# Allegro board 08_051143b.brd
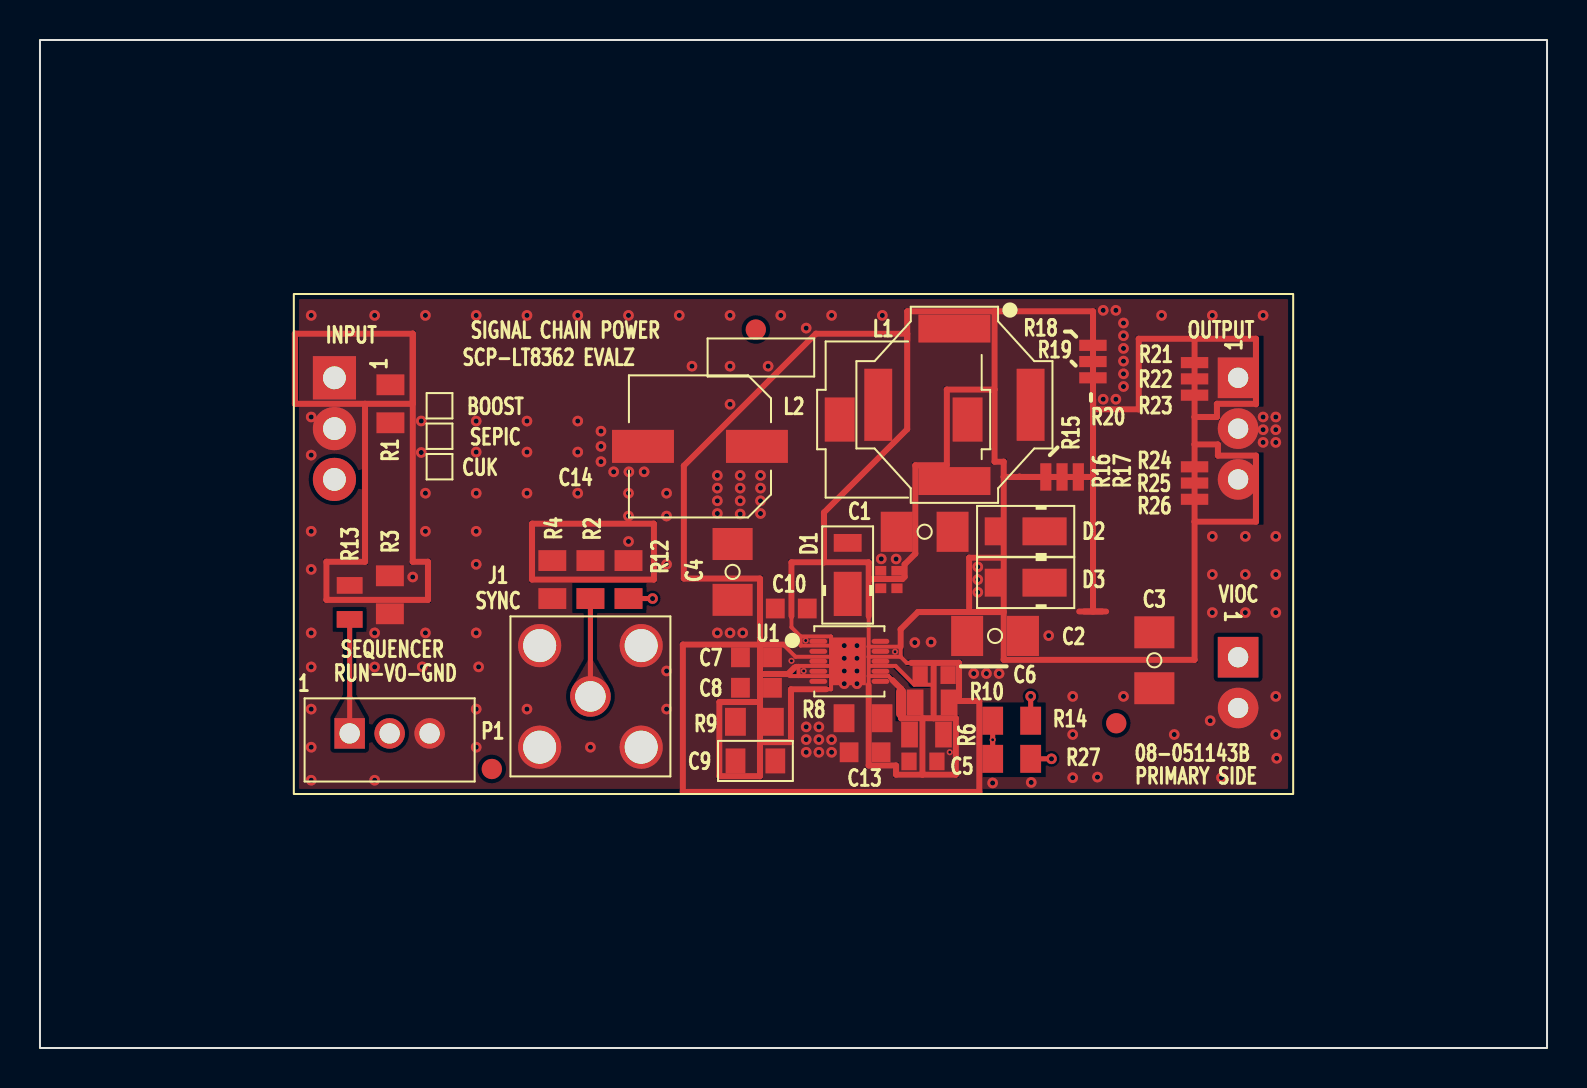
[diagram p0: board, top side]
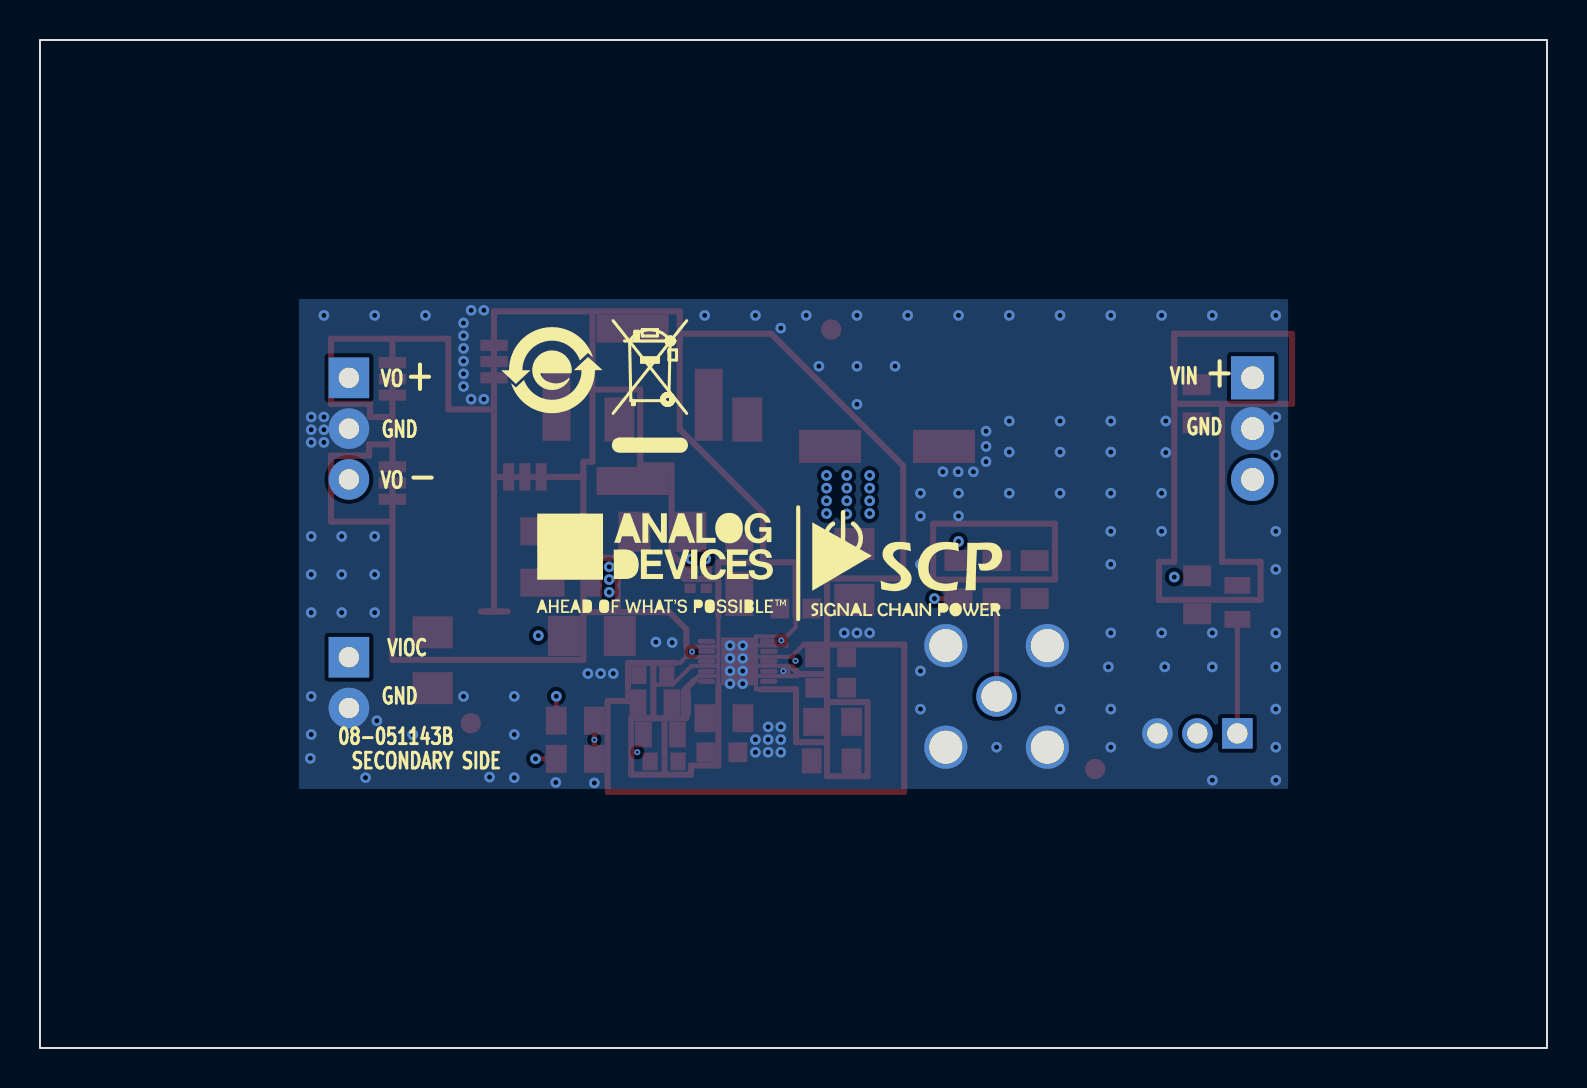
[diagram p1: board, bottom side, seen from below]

Outline 75.4 x 50.4 mm; copper layers: TOP, L2, L3, BOTTOM. Coordinates in mm from the lower left corner of the outline.
Outline path: rectangle 0,0 75.4,50.4

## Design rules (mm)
constraint set DEFAULT: min track width 0.203

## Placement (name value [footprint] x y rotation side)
C1  1uF  [C1206H71]  44.26 25.81 180 top
C2  10UF  [C1206H71]  47.78 20.6 180 top
C3  10UF  [C1206H71]  55.75 19.39 270 top
C4  10UF  [C1206H71]  34.65 23.8 270 top
C5  TBD0603  [C0603#2]  44.18 14.33 180 top
C6  0.22UF  [C0603#2]  44.74 18.65 0 top
C7  1UF  [C0603]  35.85 19.54 180 top
C8  TBD0603  [C0603]  35.85 18.01 180 top
C9  1.5NF  [C0805-2]  35.79 14.35 0 top
C10  1UF  [C0603]  37.59 21.97 0 top
C11  0.1UF  [C0402]  42.06 23.42 90 top
C12  0.1UF  [C0402]  42.88 23.42 90 top
C13  TBD0603  [C0603]  41.28 14.79 180 top
C14  33UF  [CPLSMSQ260H315]  33.02 30.08 180 top
D1  DFLS260-7  [POWERDI123]  40.41 23.65 90 top
D2  DFLS260-7  [POWERDI123]  49.32 25.83 180 top
D3  DFLS260-7  [POWERDI123]  49.32 23.27 180 top
INPUT  PBC03SBAN  [CNTHMHDRRA1X3L300W100H145]  14.73 33.51 270 top
J1  5-1814832-1  [CNTYCO1814832]  27.54 17.58 0 top
L1  6.8UH  [LSMSQ315H83]  45.75 32.16 270 top
L2  6.8UH  [LSMSQ287H138]  43.21 31.42 0 top
NOREF  -  [unnamed]  53.85 16.24 0 top
NOREF#2  -  [#2]  -137.79 189.21 0 top
NOREF#3  -  [#2]  12.7 12.7 0 top
NOREF#4  -  [#2]  62.85 37.77 180 top
NOREF#5  -  [#2]  -223.77 -182.39 0 top
NOREF#6  -  [#2]  38.28 64.9 0 top
NOREF#7  -  [#2]  92.84 143.87 0 top
NOREF#8  -  [#2]  -336.95 -273.25 0 top
NOREF#9  -  [#2]  -287.53 151.49 0 top
NOREF#10  -  [#2]  62.7 12.7 90 top
NOREF#11  -  [#2]  -336.95 -273.25 0 top
NOREF#12  -  [#2]  12.68 12.75 0 top
NOREF#13  -  [#2]  117.03 50.84 0 top
NOREF#14  -  [#2]  62.72 12.75 90 top
NOREF#15  -  [#2]  12.68 37.77 270 top
NOREF#16  -  [unnamed]  35.81 35.92 0 top
NOREF#17  -  [#2]  -187.71 -197.76 0 top
NOREF#18  -  [unnamed]  22.61 13.95 0 top
NOREF#19  -  [#2]  49.78 33.89 180 bottom
NOREF#20  -  [#2]  45.09 29.83 180 bottom
NOREF#21  -  [#2]  44.61 24.22 180 bottom
NOREF#22  -  [#2]  32 24.24 180 bottom
OUTPUT  PPPC031LGBN-RC  [CNHDRRA1X3H108]  59.94 33.51 270 top
P1  53253-0370  [CNTHMHDR1X3L315W144H224]  15.49 15.73 0 top
R1  1MEG  [R0805]  17.53 32.21 270 top
R2  0  [R0805]  27.54 23.42 90 top
R3  TBD0805  [R0805]  17.51 22.66 270 top
R4  0  [R0805]  25.63 23.42 90 top
R6  1MEG  [R0805#2]  44.35 15.68 180 top
R8  71.5K  [R0805]  41.18 16.49 180 top
R9  40.2K  [R0805]  35.74 16.31 180 top
R10  20K  [R0805#2]  44.63 17.28 0 top
R12  0  [R0805]  29.44 23.42 90 top
R13  TBD0805  [R0805#2]  15.49 22.28 90 top
R14  0  [R0805]  48.62 16.36 180 top
R15  -  [NC0402L]  50.32 28.55 270 top
R16  -  [NC0402L]  51.14 28.55 270 top
R17  -  [NC0402L]  51.95 28.55 270 top
R18  -  [NC0402L]  52.68 35.13 0 top
R19  -  [NC0402L]  52.68 34.32 0 top
R20  -  [NC0402L]  52.68 33.51 0 top
R21  -  [NC0402L]  57.77 34.27 0 top
R22  -  [NC0402L]  57.77 33.46 0 top
R23  -  [NC0402L]  57.77 32.64 0 top
R24  -  [NC0402L]  57.77 29.06 0 top
R25  -  [NC0402L]  57.77 28.25 0 top
R26  -  [NC0402L]  57.77 27.44 0 top
R27  0  [R0805]  48.62 14.46 0 top
U1  LT8362EDD#PBF  [DFN10_3X3_PAD2_38X1_64]  40.49 19.33 270 top
VIOC  PPPC021LGBN-RC  [CNTHFHDRRA1X2L220W335H108]  59.94 19.54 270 top

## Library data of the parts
C1 = CAP: Tolerance: 10; User Part Number: UPN; alternate symbols: (); part number: CAP_SM-1UF,100V,10,E023069,C1206H71; tolerance: 10
C2-C4 = CAP: Tolerance: 20; User Part Number: UPN; alternate symbols: (); part number: CAP_SM-10UF,50V,20,E035601,C1206H71; tolerance: 20
C5 C8 C13 = CAP: User Part Number: UPN; alternate symbols: (C0603L, C0603L_ALT); part number: CAP_SM-TBD0603,TBD0603,TBD0603,E000382,C0603
C6 = CAP: Tolerance: 10; User Part Number: UPN; alternate symbols: (C0603L, C0603L_ALT); part number: CAP_SM-0.22UF,25V,10,E028829,C0603; tolerance: 10
C7 C10 = CAP: User Part Number: UPN; Tolerance: 10; alternate symbols: (); part number: CAP_SM-1UF,50V,10,E034224,C0603; tolerance: 10
C9 = CAP: Tolerance: 10; User Part Number: UPN; alternate symbols: (); part number: CAP_SM-1.5NF,25V,10,E033704,C0805-2; tolerance: 10
C11 C12 = CAP: Tolerance: 10; User Part Number: UPN; alternate symbols: (C0402L_ALT); part number: CAP_SM-0.1UF,50V,10,E038292,C0402; tolerance: 10
C14 = CAPP: Tolerance: 20; User Part Number: UPN; alternate symbols: (); part number: CAPP_SM-33UF,50V,20,E035519,CPLSMSQ260H315; tolerance: 20
D1-D3 = DIOSCHOTTKY: User Part Number: UPN; Tolerance: N/A; alternate symbols: (); part number: DIOSCHOTTKY_SM-DFLS260-7,60V,N/A,E032987,POWERDI123; tolerance: N/A
INPUT = CN3P: Tolerance: N/A; User Part Number: UPN; alternate symbols: (CNTHMHDRRA1X3L300W100H145_SCP); part number: CN3P_TH-PBC03SBAN,E034137,CNTHMHDRRA1X3L300W100H145; tolerance: N/A
J1 = CNBNC5P: Tolerance: N/A; User Part Number: UPN; alternate symbols: (); part number: CNBNC5P_TH-5-1814832-1,E010606,CNTYCO1814832; tolerance: N/A
L1 = IND_4P_V11: Tolerance: 30; User Part Number: UPN; alternate symbols: (); part number: IND_4P_V11_SM-6.8UH,30,E033529,LSMSQ315H83; tolerance: 30
L2 = IND: Tolerance: 20; User Part Number: UPN; alternate symbols: (); part number: IND_SM-6.8UH,20,E033705,LSMSQ287H138; tolerance: 20
OUTPUT = CN3P: User Part Number: UPN; Tolerance: N/A; alternate symbols: (CNHDRRA1X3H108_SCP); part number: CN3P_TH-PPPC031LGBN-RC,E034111,CNHDRRA1X3H108; tolerance: N/A
P1 = CN3P: Tolerance: N/A; User Part Number: UPN; alternate symbols: (); part number: CN3P_TH-53253-0370,E033940,CNTHMHDR1X3L315W144H224; tolerance: N/A
R1 = RES: User Part Number: UPN; Tolerance: 5; alternate symbols: (); part number: RES_SM-1MEG,E033749,1/8W,5,R0805; tolerance: 5
R2 R4 R12 R14 R27 = RES: User Part Number: UPN; Tolerance: N/A; alternate symbols: (R0805L); part number: RES_SM-0,E030875,1/8W,N/A,R0805; tolerance: N/A
R3 R13 = RES: User Part Number: UPN; alternate symbols: (R0805L); part number: RES_SM-TBD0805,E004051,TBD0805,TBD0805,R0805
R6 = RES: User Part Number: UPN; Tolerance: 1; alternate symbols: (R0805L); part number: RES_SM-1MEG,E003518,1/8W,1,R0805; tolerance: 1
R8 = RES: User Part Number: UPN; Tolerance: 1; alternate symbols: (R0805L); part number: RES_SM-71.5K,E005326,1/8W,1,R0805; tolerance: 1
R9 = RES: User Part Number: UPN; Tolerance: 0.1; alternate symbols: (R0805L); part number: RES_SM-40.2K,E018845,1/5W,0.1,R0805; tolerance: 0.1
R10 = RES: User Part Number: UPN; Tolerance: 1; alternate symbols: (R0805L); part number: RES_SM-20K,E003539,1/8W,1,R0805; tolerance: 1
R15-R26 = NC2P: User Part Number: UPN; Tolerance: N/A; alternate symbols: (); part number: NC2P_SM-NC0402L,E033984,NC0402L; tolerance: N/A
U1 = ICLT8362: Tolerance: N/A; User Part Number: UPN; alternate symbols: (); part number: ICLT8362_SM-LT8362EDD#PBF,E033516,DFN10_3X3_PAD2_38X1_64; tolerance: N/A
VIOC = CN2P: Tolerance: N/A; User Part Number: UPN; alternate symbols: (CNTHFHDRRA1X2L220W335H108_SCP); part number: CN2P_TH-PPPC021LGBN-RC,E034113,CNTHFHDRRA1X2L220W335H108; tolerance: N/A

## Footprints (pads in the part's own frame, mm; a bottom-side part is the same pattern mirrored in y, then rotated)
C0402
  rect 0.483x0.559 smd: 1(-0.438,0) 2(0.438,0)
C0603
  rect 0.94x0.991 smd: 1(-0.8,0) 2(0.8,0)
C0603#2
  rect 0.762x0.889 smd: 1(-0.699,0) 2(0.699,0)
C0805-2
  rect 0.991x1.245 smd: 1(-0.995,0) 2(0.995,0)
C1206H71
  rect 1.6x2.007 smd: 1(-1.397,0) 2(1.397,0)
CNHDRRA1X3H108
  rect 2.032x2.032 hole 1.016: 1(0,0)
  round 2.032 hole 1.016: 2(2.54,0) 3(5.08,0)
CNTHFHDRRA1X2L220W335H108
  rect 2.032x2.032 hole 1.016: 1(0,0)
  round 2.032 hole 1.016: 2(2.54,0)
CNTHMHDR1X3L315W144H224
  rect 1.524x1.524 hole 1.016: 1(0,0)
  round 1.524 hole 1.016: 2(2,0) 3(4,0)
CNTHMHDRRA1X3L300W100H145
  rect 2.159x2.159 hole 1.143: 1(0,0)
  round 2.159 hole 1.143: 2(2.54,0) 3(5.08,0)
CNTYCO1814832
  round 2.032 hole 1.524: 1(0,0)
  round 2.159 hole 1.651: 2(-2.54,2.54) 3(2.54,2.54) 4(2.54,-2.54) 5(-2.54,-2.54)
CPLSMSQ260H315
  rect 3.099x1.651 smd: N(2.85,0) P(-2.85,0)
DFN10_3X3_PAD2_38X1_64
  oval 0.254x0.889 smd: 1(-1,-1.555) 2(-0.5,-1.555) 3(0,-1.555) 4(0.5,-1.555) 5(1,-1.555) 6(1,1.555) 7(0.5,1.555) 8(0,1.555) 9(-0.5,1.555) 10(-1,1.555)
  rect 2.388x1.651 smd: PAD(0,0)
LSMSQ287H138
  rect 1.499x2.21 smd: 1(-3.199,0) 2(3.199,0)
LSMSQ315H83
  rect 1.397x3.607 smd: 1(-3.811,0) 3(3.811,0)
  rect 3.607x1.397 smd: 2(0,-3.811) 4(0,3.811)
NC0402L
  rect 0.572x0.559 smd: 1(-0.4,0) 2(0.4,0)
POWERDI123
  rect 0.889x1.397 smd: A(1.606,0)
  rect 2.21x1.397 smd: C(-0.945,0)
R0805
  rect 1.041x1.397 smd: 1(-0.95,0) 2(0.95,0)
R0805#2
  rect 0.838x1.295 smd: 1(-0.85,0) 2(0.85,0)
unnamed
  round 1.016 smd: (0,0)

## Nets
AGND: C2.2(N2) C3.2(N2) C4.2(N2) C6.2(N2) C7.2(N2) C8.2(N2) C9.2(N2) C10.2(N2) C13.2(N2) C14.N(N2) D1.C INPUT.2 J1.2 J1.3 J1.4 J1.5(SH4) OUTPUT.2 P1.3(N3) R3.2(N2) R4.1 R8.2(N2) R10.2(N2) R18.2(N2) R19.2(N2) R20.2(N2) U1.4 U1.PAD VIOC.2(N2)
INTVCC: C7.1 R12.1 U1.3
OUT: C2.1 C3.1 D2.C D3.C P1.2 R14.1 R15.2(N2) R16.2(N2) R17.2(N2) R21.1 R22.1 R23.1 R24.1 R25.1 R26.1
RUN: P1.1 R13.1
SYNC: J1.1 R2.1
UNNAMED_2_CAP_I16_N1: C9.1 R9.2(N2)
UNNAMED_2_CAP_I18_N1: C6.1 U1.8
UNNAMED_2_CAP_I26_N1: C8.1 R9.1 U1.5
UNNAMED_2_CAP_I28_N1: C1.1 C11.1 C12.1 D2.A(P) L1.3 L2.2(N2) U1.10
UNNAMED_2_CAP_I28_N2: C1.2(N2) C11.2(N2) C12.2(N2) D1.A(P) D3.A(P) L1.1
UNNAMED_2_CAP_I41_N1: C5.2(N2) C13.1 R6.2(N2) R8.1 U1.6
UNNAMED_2_CAP_I42_N1: C5.1 R6.1 R14.2(N2) R27.1
UNNAMED_2_ICLT8362_I21_EN: R1.2(N2) R3.1 R13.2(N2) U1.1
UNNAMED_2_ICLT8362_I21_RT: R10.1 U1.7
UNNAMED_2_ICLT8362_I21_SYNC: R2.2(N2) R4.2(N2) R12.2(N2) U1.9
UNNAMED_2_IND4PV11_I25_N4: L1.4(N4) R15.1 R16.1 R17.1 R18.1 R19.1 R20.1
V+: C4.1 C10.1 C14.P INPUT.1 L1.2 L2.1 R1.1 U1.2(VIN)
VIOC: R27.2(N2) VIOC.1
VO+: OUTPUT.1 R21.2(N2) R22.2(N2) R23.2(N2)
VO-: OUTPUT.3(N3) R24.2(N2) R25.2(N2) R26.2(N2)

Pads without a net: INPUT 3

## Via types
v1: diameter 0.305, hole 0.152, TOP to BOTTOM, 6 vias
v2: diameter 0.533, hole 0.254, TOP to BOTTOM, 153 vias

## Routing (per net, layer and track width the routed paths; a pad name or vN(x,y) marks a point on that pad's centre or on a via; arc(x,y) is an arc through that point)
AGND: length 0
  BOTTOM w0: 28.4,24.12 28.4,24.12
  vias: v1(38.21,18.85) v2(13.57,36.63) v2(13.57,31.55) v2(13.57,29.65) v2(13.57,25.84) v2(13.57,23.93) v2(13.57,20.76) v2(13.57,19.05) v2(13.57,16.95) v2(13.57,15.04) v2(13.57,13.39) v2(16.74,36.63) v2(16.74,20.76) v2(16.74,19.05) v2(16.74,13.39) v2(19.08,31.35) v2(19.08,29.78) v2(19.13,19.06) v2(19.28,36.63) v2(19.28,27.74) v2(19.28,25.84) v2(19.28,20.76) v2(21.82,36.63) v2(21.82,31.35) v2(21.82,29.8) v2(21.82,27.74) v2(21.82,25.84) v2(21.82,24.18) v2(21.82,20.76) v2(21.82,16.95) v2(21.82,15.04) v2(21.95,19.06) v2(24.36,36.63) v2(24.36,31.35) v2(24.36,29.8) v2(24.36,27.74) v2(24.36,16.95) v2(26.9,36.63) v2(26.9,31.35) v2(26.9,29.8) v2(26.9,27.74) v2(27.54,15.04) v2(28.07,30.84) v2(28.07,30.08) v2(28.07,29.32) v2(28.7,28.81) v2(29.44,36.63) v2(29.46,28.81) v2(29.44,27.74) v2(29.44,26.6) v2(30.23,28.81) v2(31.35,27.74) v2(31.35,26.6) v2(31.35,24.18) v2(31.35,18.85) v2(31.35,16.95) v2(31.98,36.63) v2(32.62,34.09) v2(33.89,20.76) v2(34.52,36.63) v2(34.52,34.09) v2(34.52,32.19) v2(34.52,20.76) v2(35.16,20.76) v2(36.43,34.09) v2(37.06,36.63) v2(38.33,36) v2(38.33,16.06) v2(38.33,15.42) v2(38.33,14.79) v2(38.97,16.06) v2(38.97,15.42) v2(38.97,14.79) v2(39.6,36.63) v2(39.6,15.42) v2(39.6,14.79) v2(40.24,20.12) v2(40.24,19.49) v2(40.24,18.85) v2(40.24,18.22) v2(40.87,20.12) v2(40.87,19.49) v2(40.87,18.85) v2(40.87,18.22) v2(42.14,36.63) v2(43.77,20.27) v2(44.58,20.3) v2(46.72,18.72) v2(47.35,18.72) v2(47.66,13.25) v2(47.99,18.72) v2(49.59,13.28) v2(51.67,17.58) v2(51.67,15.68) v2(51.67,13.52) v2(52.91,13.54) v2(53.19,36.88) v2(53.19,32.44) v2(53.83,36.88) v2(53.83,32.44) v2(54.21,36.25) v2(54.21,35.61) v2(54.21,34.98) v2(54.21,34.34) v2(54.21,33.71) v2(54.21,33.07) v2(54.21,17.58) v2(56.11,36.63) v2(56.75,15.68) v2(58.55,16.36) v2(58.65,36.63) v2(58.65,25.58) v2(58.65,23.68) v2(58.65,21.77) v2(59.11,13.52) v2(60.31,25.58) v2(60.31,23.68) v2(60.31,21.77) v2(61.19,36.63) v2(61.19,31.55) v2(61.19,30.92) v2(61.19,30.28) v2(61.83,31.55) v2(61.83,30.92) v2(61.83,30.28) v2(61.83,25.58) v2(61.83,23.68) v2(61.83,21.77) v2(61.83,17.58) v2(61.83,15.68) v2(61.87,14.48)
INTVCC: length 9.4
  TOP w0.254: R12.1 v2(30.65,22.47)
  L3 w0.254: v2(30.65,22.47) 34.48,22.47 v1(37.6,19.36)
OUT: length 41.4
  TOP w0.254: R14.1 v2(49.57,17.58)
  L3 w0.254: v2(49.57,17.58) 50.47,18.49 v2(50.47,20.62) 46.62,20.62 39.57,13.57 19.65,13.57 P1.2
RUN: length 5.7
  TOP w0.254: P1.1 R13.1
SYNC: length 4.9
  TOP w0.254: R2.1 J1.1
UNNAMED_2_CAP_I28_N2:
  vias: v2(42.09,24.46) v2(42.83,24.45) v2(46.92,24.06) v2(46.92,23.42) v2(46.92,22.79)
UNNAMED_2_CAP_I42_N1: length 4.3
  TOP w0.254: R27.1 47.66,14.46 v1(47.66,15.41) 47.67,15.41 R14.2
  L3 w0.254: v1(45.52,14.79) 46.14,15.41 v1(47.66,15.41)
UNNAMED_2_ICLT8362_I21_EN: length 21
  L3 w0.254: v1(38.31,20.37) 35.13,23.55 v2(18.65,23.55)
UNNAMED_2_ICLT8362_I21_SYNC: length 15.6
  L3 w0.254: v1(42.78,19.82) 37.27,25.33 v2(29.44,25.33)
V+:
  vias: v2(33.89,28.63) v2(33.89,27.99) v2(33.89,27.36) v2(33.89,26.72) v2(35.03,28.63) v2(35.03,27.99) v2(35.03,27.36) v2(35.03,26.7) v2(36.05,28.63) v2(36.05,27.99) v2(36.05,27.36) v2(36.05,26.72)
VIOC: length 12.5
  TOP w0.254: R27.2 v2(50.61,14.46)
  L3 w0.254: v2(50.61,14.46) 52.36,14.46 57.44,19.54 VIOC.1

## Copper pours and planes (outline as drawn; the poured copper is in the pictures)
AGND on TOP: 12.96,12.96 12.96,32.06 16.11,32.06 16.11,24.46 14.18,24.46 14.18,22.25 19.56,22.25 19.56,24.46 18.8,24.46 18.8,35.87 12.96,35.87 12.96,37.45 62.44,37.45 62.44,12.96 47.15,12.96 47.15,13.54 50.32,13.54 50.32,17.28 47.15,17.28 47.15,17.5 46.13,17.5 46.13,19.41 43.35,19.41 43.21,19.56 43.21,20.86 43.99,21.64 48.06,21.64 48.06,19.26 57.92,19.26 57.92,26.17 61.21,26.17 61.21,29.77 59.09,29.77 59.09,30.33 57.92,30.33 57.92,31.4 59.04,31.4 59.04,32.06 61.21,32.06 61.21,35.61 54.82,35.61 54.82,32.08 52.84,32.08 52.84,36.99 43.24,36.99 43.24,35.87 38.75,35.87 32.06,29.17 32.06,23.32 35.87,23.32 35.87,20.32 32.01,20.32 32.01,12.96 ; 2 cut-outs
AGND on TOP: 32.32,12.96 32.32,20.02 35.87,20.02 35.87,17.45 33.84,17.45 33.84,13.44 36.18,13.44 36.18,15.14 37.73,15.14 37.73,17.78 39.39,17.78 39.44,17.83 39.68,17.83 39.68,20.68 38.1,20.68 37.7,21.08 37.7,21.48 37.75,21.53 37.75,24.13 41.31,24.13 41.31,21.53 41.36,21.48 41.36,18.25 41.31,18.2 41.31,13.97 42.68,13.97 42.68,13.52 45.97,13.52 45.97,16.64 44.86,16.64 44.86,19.1 45.9,19.1 45.9,17.2 46.84,17.2 46.84,12.96
AGND on BOTTOM: 12.95,12.95 12.95,37.45 62.45,37.45 62.45,12.95 ; 3 cut-outs
AGND on L2: 12.96,12.96 12.96,37.45 62.44,37.45 62.44,12.96 ; 3 cut-outs
AGND on L3: 12.96,12.96 12.96,31.91 27.6,31.91 33.57,25.94 36.96,25.94 36.96,29.07 29.76,36.27 12.96,36.27 12.96,37.45 62.44,37.45 62.44,12.96 ; 1 cut-out
INTVCC on TOP: 36.18,18.85 36.18,20.02 37.2,20.02 37.76,19.46 39.48,19.46 39.48,19.21 37.72,19.21 37.69,19.18 37.36,18.85
INTVCC on TOP: 28.75,22.99 28.75,21.95 30.14,21.95 30.14,22.99
OUT on TOP: 48.37,19.56 48.37,28.4 52.53,28.4 52.53,21.98 51.93,21.98 51.84,21.89 51.84,21.76 51.93,21.67 53.4,21.67 53.49,21.76 53.49,21.89 53.4,21.98 52.84,21.98 52.84,31.78 55.12,31.78 55.12,35.31 57.61,35.31 57.61,19.56
RUN on TOP: 14.85,21.84 14.85,21.01 16.13,21.01 16.13,21.84
SYNC on TOP: 26.84,22.99 26.84,21.95 28.23,21.95 28.23,22.99
UNNAMED_2_CAP_I16_N1 on TOP: 34.14,13.74 34.14,17.15 35.87,17.15 35.87,13.74
UNNAMED_2_CAP_I18_N1 on TOP: 43.74,18.22 42.75,19.21 41.56,19.21 41.56,19.46 43.02,19.46 43.37,19.11 44.56,19.11 44.56,18.22
UNNAMED_2_CAP_I26_N1 on TOP: 36.18,15.45 36.18,18.55 37.43,18.55 37.48,18.49 39.48,18.49 39.48,18.09 39.39,18.09 39.39,18.09 37.42,18.09 37.42,15.45
UNNAMED_2_CAP_I28_N1 on TOP: 41.56,20.17 41.56,21.48 41.61,21.53 41.61,23.3 43.21,23.3 43.41,23.49 43.41,24.12 43.95,24.65 43.95,28.98 45.52,28.98 45.52,32.77 47.61,32.77 47.61,29.16 48.06,29.16 48.06,24.67 46.34,24.67 46.34,21.95 43.86,21.95 42.91,21 42.91,20.17
UNNAMED_2_CAP_I28_N2 on TOP: 46.64,21.95 46.64,24.36 48.06,24.36 48.06,21.95
UNNAMED_2_CAP_I28_N2 on TOP: 41.61,23.6 41.61,24.44 39.38,24.44 39.38,26.71 43.54,30.88 43.54,36.68 47.61,36.68 47.61,33.07 45.22,33.07 45.22,29.29 43.64,29.29 43.64,24.78 43.15,24.29 43.15,23.6
UNNAMED_2_CAP_I28_N2 on L3: 41.79,22.18 41.79,25.02 47.2,25.02 47.2,22.18
UNNAMED_2_CAP_I41_N1 on TOP: 42.98,13.82 42.98,14.28 41.61,14.28 41.61,18.2 41.56,18.25 41.56,18.49 42.4,18.49 42.8,18.09 42.8,16.34 44,16.34 44,13.82
UNNAMED_2_CAP_I42_N1 on TOP: 44.3,13.82 44.3,16.34 45.67,16.34 45.67,13.82
UNNAMED_2_ICLT8362_I21_EN on TOP: 14.48,22.56 14.48,24.16 16.41,24.16 16.41,32.06 18.5,32.06 18.5,24.16 19.26,24.16 19.26,22.56
UNNAMED_2_ICLT8362_I21_RT on TOP: 43.34,16.64 43.34,17.93 42.57,18.7 42.49,18.7 42.49,18.7 41.56,18.7 41.56,19 42.68,19 43.62,18.06 44.56,18.06 44.56,16.64
UNNAMED_2_ICLT8362_I21_SYNC on TOP: 24.77,23.57 24.77,26.06 30.56,26.06 30.56,23.57
UNNAMED_2_IND4PV11_I25_N4 on TOP: 48.37,28.71 48.37,29.47 47.91,29.47 47.91,36.68 52.53,36.68 52.53,28.71 49.09,28.71 49.07,28.73 48.94,28.73 48.91,28.71
V+ on TOP: 37.85,19.66 37.19,20.32 36.18,20.32 36.18,23.63 32.37,23.63 32.37,29.05 38.88,35.56 43.24,35.56 43.24,31 39.07,26.84 39.07,24.44 37.45,24.44 37.45,21.53 37.5,21.48 37.5,20.99 37.95,20.54 37.95,20.02 39.48,20.02 39.48,19.66
V+ on TOP: 12.96,32.36 12.96,35.56 18.5,35.56 18.5,32.36
V+ on L3: 33.7,26.24 27.73,32.21 12.96,32.21 12.96,35.97 29.64,35.97 36.66,28.95 36.66,26.24
VO+ on TOP: 57.92,31.7 57.92,35.31 60.96,35.31 60.96,32.36 58.73,32.36 58.73,31.7
VO- on TOP: 57.92,26.47 57.92,30.03 58.78,30.03 58.78,29.47 60.96,29.47 60.96,26.47

Small or netless copper shapes (teardrops, artwork), in the pictures only: 5 on TOP

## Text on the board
Ref Des/Silkscreen Bottom: GND | VIN | SECONDARY SIDE | VIOC | 08-051143B | VO | + | -
User.Comments: AND PLACE MARK ON TICK BOX IN THE PRIMARY SIDE | 5.    INSTALL SOLDER BLOB USING THE TABLE BELOW (SEE DETAIL A) | 4.    RoHS COMPLIANCE: ASSEMBLY VENDOR SHOULD ASSURE COMPLIANCE | WITH LEAD-FREE AND RoHS PCB ASSEMBLY STANDARDS (EU RoHS | DIRECTIVE 2002/95/EC). | SCALE FACTOR: 1:4 | BOM | 05-051143-01-B | 05-051143-02-B | 05-051143-03-B | DETAIL A | R15, R16, R17, R24, R25, R26 | PARTS | R18, R19, R20, R21, R22, R23 | R21, R22, R23 | TICK BOX | CUK | SEPIC | BOOST
Ref Des/Silkscreen Top: INPUT | SEQUENCER | RUN-VO-GND | CUK | P1 | BOOST | SEPIC | J1 | SYNC | SCP-LT8362 EVALZ | SIGNAL CHAIN POWER | C14 | C9 | R9 | C7 | C8 | U1 | C10 | L2 | R8 | C1 | C13 | L1 | C5 | R10 | C6 | R18 | R19 | R14 | C2 | R27 | D2 | D3 | R20 | R25 | C3 | R24 | R26 | R22 | R23 | R21 | 08-051143B | PRIMARY SIDE | OUTPUT | VIOC | R13 | R1 | R3 | R4 | R2 | R12 | C4 | D1 | R6 | R15 | R16 | R17
PAGE_OUTLINE: B | AS PER ECR-086393 | 06MAY19 | J VIERNES
DIMENSION: -0.819 | 0.165 | "0" | REF | SEE FAB NOTE 15 | DIA MAX | -0.080 | 1.889
User.15: ROHS COMPLIANCE NOTE: | ENIG (Electroless Nickel/Immersion Gold) | PER IPC-4552 LATEST REVISION | HOMOGENOUS MATERIALS IN THIS BOARD SHALL BE COMPLIANT | THE EU RoHS DIRECTIVE 2002/95/EC | 15.    THRU VIAS TO BE FILLED WITH SOLDERMASK. | CORE | 0.035"
User.17: L2 | 08-      -07
User.18: 08-      -08 | L3 | L3 SIGNAL
User.23: INPUT | P1 | J1 | C14 | C9 | R9 | C7 | C8 | U1 | C10 | L2 | R8 | C1 | C13 | L1 | C5 | R10 | C6 | R18 | R19 | R14 | C2 | R27 | D2 | D3 | R20 | R25 | C3 | R24 | R26 | R22 | R23 | R21 | OUTPUT | VIOC | R13 | R1 | R3 | R4 | R2 | R12 | C4 | D1 | C11 | C12 | R6 | R15 | R16 | R17
User.45: FIGURE | SIZE | 6.0 | 10.0 | 40.0 | 45.0 | 60.0 | 65.0 | PLATED | FINISHED HOLES IN MILS | ALL UNITS ARE IN MILS | QTY | 6 | 153 | 8 | 3 | 1 | 4 | TOLERANCE/NOTES
